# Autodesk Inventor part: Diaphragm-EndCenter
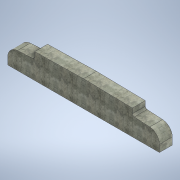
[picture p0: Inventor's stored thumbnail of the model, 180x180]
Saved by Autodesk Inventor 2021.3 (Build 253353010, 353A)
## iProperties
Created: 2021-10
Part Number: Diaphragm-EndCenter
Material: Concrete, Precast
Document SubType Name: Modeling
Designer: u1426
Density: 2.40731 g/cm^3
Appearance: Smooth Precast Structural
Author: u1426
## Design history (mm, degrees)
sketch "Sketch1"
  geometry: L1 (-762, 1295.4)-(-762, 1261.45); L2 (-726.164, 1223.417)-(-419.726, 1205.177); L3 (-228.6, 1002.336)-(-228.6, 863.6); L4 (-3225.8, 863.6)-(-3225.8, 1002.336); L5 (-2692.4, 1261.45)-(-2692.4, 1295.4); L6 (-2728.236, 1223.417)-(-3034.674, 1205.177); L7 (-3225.8, 863.6)-(-228.6, 863.6); L8 (-3302, 1295.4)-(-3302, 152.4); L9 (-152.4, 1295.4)-(-152.4, 152.4); L10 (-2692.4, 1295.4)-(-3302, 1295.4); L11 (-762, 1295.4)-(-152.4, 1295.4); L12 (-3302, 152.4)-(-4872.129, 152.4); L13 (-152.4, 152.4)-(-1248.139, 152.4); L14 (-2692.4, 1295.4)-(-2692.4, 1357.884); L15 (-762, 1357.884)-(-762, 1295.4); L16 (-2692.4, 1357.884)-(-1727.2, 1377.188); L17 (-1727.2, 1377.188)-(-762, 1357.884); A1 r 203.2 centre (-431.8, 1002.336) between (-228.6, 1002.336) and (-419.726, 1205.177); A2 r 38.1 centre (-723.9, 1261.45) between (-762, 1261.45) and (-726.164, 1223.417); A3 r 203.2 centre (-3022.6, 1002.336) between (-3034.674, 1205.177) and (-3225.8, 1002.336); A4 r 38.1 centre (-2730.5, 1261.45) between (-2728.236, 1223.417) and (-2692.4, 1261.45); 5 further points
  constraints: 34 end point, 8 point on circle, 8 point on line, 8 tangent, 5 vertical, 4 centre point, 2 horizontal, 2 perpendicular, 1 parallel
  dimensions: "d12" = 69.85 distance of L1.start point (-762, 1225.55); "d16" = 31.75 vertical distance of point (-762, 1225.55) point (-228.6, 1193.8); "d23" = 203.2 radius of A1; "d24" = 38.1 radius of A2; "d68" = 533.4 horizontal distance of point (-2692.4, 1225.55) point (-3225.8, 1193.8); "d69" = 31.75 vertical distance of point (-2692.4, 1225.55) point (-3225.8, 1193.8); "d70" = 69.85 distance of point (-2692.4, 1225.55) L5.end; "d78" = 203.2 radius of A3; "d79" = 38.1 radius of A4; "d82" = 76.2 distance between parallel lines of L3 L9; "d83" = 76.2 distance between parallel lines of L4 L8; "d84" = 1143 distance of L9.start L9.end; "d85" = 1143 distance of L8.start L8.end (= d84); "d88" = 0 distance between parallel lines of L13 L12; "d89" = 3149.6 distance between parallel lines of L9 L8; "d90" = 62.484 distance of L5.end L14.end; "d91" = 152.4 distance from line of point (0, 0) L13; "d92" = 152.4 distance from line of point (0, 0) L9; "d93" = 533.4 distance between parallel lines of L3 L1; "d96" = 965.2 horizontal distance of L14.end L16.end; "d97" = 965.2 horizontal distance of L16.end L15.start (derived); "d98" = 19.304 vertical distance of L14.end L16.end (= 0.02 x d96); "d99" = 19.304 vertical distance of L16.end L15.start (= 0.02 x d97); "d100" = 62.484 distance of L15.start L1.start (derived); "d101" = 431.8 distance from line of L4.start L10 (= d102); "d102" = 431.8 distance from line of L3.end L11
extrude "Extrusion9" new body sketch "Sketch1" stored distance "d94" = 254; taper "d95" = 0 deg
body "Solid4"
